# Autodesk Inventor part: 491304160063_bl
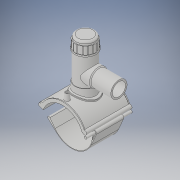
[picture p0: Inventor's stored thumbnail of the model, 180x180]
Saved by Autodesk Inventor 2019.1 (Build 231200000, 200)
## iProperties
Created: 2017-07
Part Number: 491304160063_bl
Material: Generic
Description: PLASSON TAPPING TEE SADDLE 160mm x 63mm
Document SubType Name: Modeling
Designer: KIM
Mass: 1712.7 g
Surface Area: 2671.49 cm^2
Volume: 1712.7 cm^3
Density: 1 g/cm^3
Appearance: Default
Author: KIM
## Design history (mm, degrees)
derived "491304.ipt"
feature "Solid1::491304.ipt" dims "ScaleForDerivedMember" = 10
feature "Solid2::491304.ipt" dims "ScaleForDerivedMember" = 10
feature "Solid4::491304.ipt" dims "ScaleForDerivedMember" = 10
feature "Solid5::491304.ipt" dims "ScaleForDerivedMember" = 10
tag "TaggingFeature1"
body "Solid1"
body "Solid2"
other parameters: "d1" = 101.118 [user parameter], "d2" = 276.8 [user parameter], "d4" = 176 [user parameter], "d5" = 0 [user parameter], "d6" = 0.1 [user parameter], "d8" = 0 [user parameter], "d40" = 96 [user parameter], "d41" = 97.65 [user parameter], "d43" = 0 [user parameter], "d45" = 0 [user parameter], "d47" = 156.159 [user parameter], "d78" = 115 [user parameter], "d79" = 15 [user parameter], "d80" = 70.4 [user parameter], "d82" = 5 deg [user parameter], "d84" = 4 [user parameter], "d85" = 14 [user parameter], "d86" = 0 [user parameter], "d87" = 3 [user parameter], "d88" = 0 [user parameter], "d97" = 3.52 [user parameter], "d98" = 0 [user parameter], "d102" = 1.6 [user parameter], "d120" = 140 deg [user parameter], "d123" = 606.708 [user parameter], "d126" = 0 [user parameter], "d153" = 176 [user parameter], "d154" = 0 [user parameter], "d159" = -11.7764 [user parameter], "d162" = 105.6 [user parameter], "d163" = 0 [user parameter], "d169" = 4.0905 [user parameter], "d172" = 0 [user parameter], "d173" = 1 [user parameter], "d176" = 20 deg [user parameter], "d177" = 11.2 [user parameter], "d180" = 0 [user parameter], "d184" = 8.96 [user parameter], "d187" = 88 [user parameter], "d188" = 15 [user parameter], "d189" = 11.2 [user parameter], "d190" = 0 [user parameter], "d195" = 90 deg [user parameter], "d197" = 0 [user parameter], "d199" = 0 [user parameter], "d200" = 11.2 [user parameter], "d202" = 0 [user parameter], "d203" = 195 [user parameter], "d206" = 75.6 [user parameter], "d207" = 146.25 [user parameter], "d208" = 152.1 [user parameter], "d209" = 181.35 [user parameter], "d210" = 76.86 [user parameter], "d212" = 72.45 [user parameter], "d213" = 39.15 [user parameter], "d216" = 0 [user parameter], "d217" = 16 [user parameter], "d218" = 8 [user parameter], "d219" = 1.6 [user parameter], "d224" = 0 [user parameter], "d259" = 50.4 [user parameter], "d260" = 63 [user parameter], "d263" = 173 [user parameter], "d265" = 0 [user parameter], "d267" = 13.00006 [user parameter], "d268" = 2.60001 [user parameter], "d269" = 2.60001 [user parameter], "d271" = 2.60001 [user parameter], "d273" = 0 [user parameter], "d274" = 23.56194 [user parameter], "d275" = 128 [user parameter], "d277" = 64 [user parameter], "d278" = 256 [user parameter], "d280" = 0 [user parameter], "d283" = 0 [user parameter], "d285" = 0 [user parameter], "d290" = 16 [user parameter], "d293" = 88 [user parameter], "d294" = 82.4 [user parameter], "d296" = 24 [user parameter], "d299" = 75 [user parameter], "d300" = 3 [user parameter], "d301" = 5 [user parameter], "d303" = 81.9 [user parameter], "d304" = 69.3 [user parameter], "d305" = 45 deg [user parameter], "d306" = 50.4 [user parameter], "d308" = 96 [user parameter], "d310" = 1 [user parameter], "B" = 173 [user parameter], "L" = 176 [user parameter], "d_t" = 6 [user parameter], "H2" = 195 [user parameter], "H1" = 75 [user parameter], "d_1" = 63 [user parameter]
